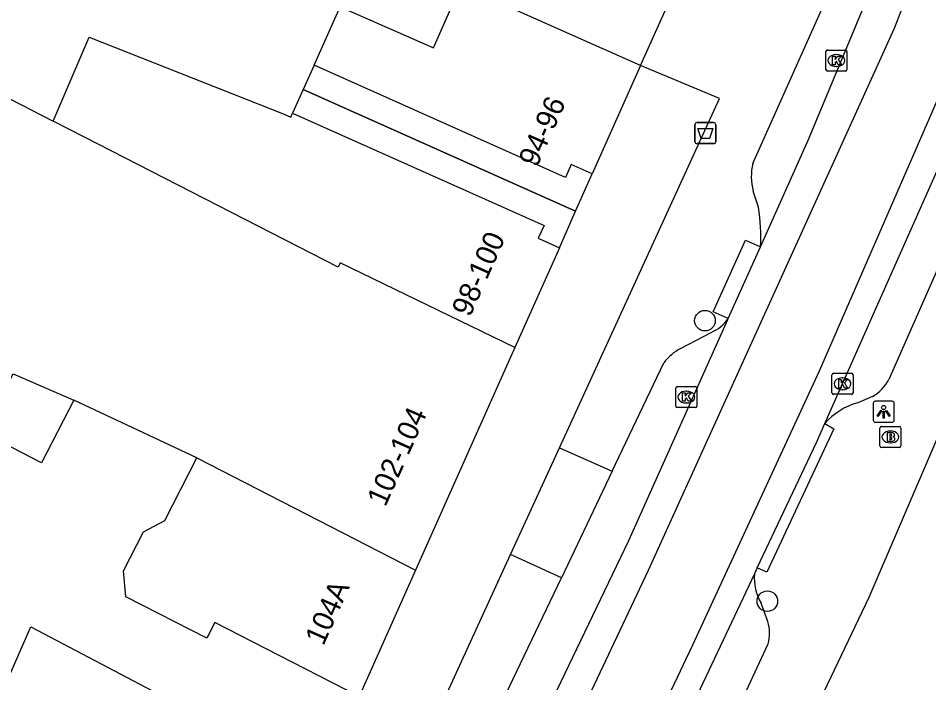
# Model space of a CAD drawing. Extents: x 160356 to 161355, y 381727 to 382845.
# Drawn here: x 160820.98 to 160864.31, y 382307.98 to 382339.61 of the extents above; entities that cross this region are included whole.
import ezdxf

# ---------------------------------------------------------------- set-up
doc = ezdxf.new("R2010")
doc.units = 0
for name, color, linetype in [('IMGEO_Afvalbak', 7, 'Continuous'), ('IMGEO_Boom', 7, 'Continuous'), ('IMGEO_Brandkraan', 7, 'Continuous'), ('IMGEO_Kolk', 7, 'Continuous'), ('IMGEO_Lichtpunt', 7, 'Continuous'), ('IMGEO_Pand', 7, 'Continuous'), ('IMGEO_Pand_nummerreeks', 7, 'Continuous'), ('IMGEO_Pand_overbouw', 7, 'Continuous'), ('IMGEO_Rijbaan_lokaal_gesloten', 7, 'Continuous'), ('IMGEO_Voetpad_open', 7, 'Continuous')]:
    doc.layers.add(name, color=color, linetype=linetype)

msp = doc.modelspace()

# ---------------------------------------------------------------- linework, layer by layer
at = {"layer": 'IMGEO_Afvalbak'}
for p, q in [((160853.179, 382333.741), (160853.179, 382334.541)), ((160853.179, 382334.541), (160853.179, 382333.741)), ((160853.279, 382334.641), (160854.069, 382334.641)), ((160854.069, 382334.641), (160853.279, 382334.641)), ((160854.169, 382334.541), (160854.169, 382333.741)), ((160854.169, 382333.741), (160854.169, 382334.541)), ((160854.069, 382333.641), (160853.279, 382333.641)), ((160853.279, 382333.641), (160854.069, 382333.641))]:
    msp.add_line(p, q, dxfattribs=at)
msp.add_lwpolyline([(160853.322, 382334.355), (160854.026, 382334.355), (160853.877, 382333.885), (160853.471, 382333.885), (160853.322, 382334.355)], dxfattribs=at)
for centre, start, end in [((160853.279, 382334.541), 90, 180), ((160853.279, 382334.541), 90, 180), ((160854.069, 382334.541), 0, 90), ((160854.069, 382334.541), 360, 90), ((160853.279, 382333.741), 180, 270), ((160853.279, 382333.741), 180, 270), ((160854.069, 382333.741), 270, 0), ((160854.069, 382333.741), 270, 0)]:
    msp.add_arc(centre, 0.1, start, end, dxfattribs=at)
at = {"layer": 'IMGEO_Boom'}
for centre in [(160853.654, 382325.214), (160856.624, 382311.862)]:
    msp.add_circle(centre, 0.489, dxfattribs=at)
at = {"layer": 'IMGEO_Brandkraan'}
for p, q in [((160861.978, 382319.251), (160861.978, 382320.103)), ((160862.053, 382320.177), (160862.905, 382320.177)), ((160862.979, 382320.103), (160862.979, 382319.251)), ((160862.466, 382319.957), (160862.491, 382319.957)), ((160862.905, 382319.177), (160862.053, 382319.177)), ((160862.489, 382319.397), (160862.464, 382319.397))]:
    msp.add_line(p, q, dxfattribs=at)
for points in [[(160861.978, 382319.251), (160861.978, 382320.103)], [(160862.053, 382320.177), (160862.905, 382320.177)], [(160862.979, 382320.103), (160862.979, 382319.251)], [(160862.326, 382319.877), (160862.326, 382319.477), (160862.539, 382319.477)], [(160862.557, 382319.877), (160862.326, 382319.877)], [(160862.505, 382319.796), (160862.451, 382319.796), (160862.451, 382319.72)], [(160862.451, 382319.72), (160862.504, 382319.72)], [(160862.513, 382319.644), (160862.451, 382319.644), (160862.451, 382319.563)], [(160862.451, 382319.563), (160862.513, 382319.563)], [(160862.905, 382319.177), (160862.053, 382319.177)]]:
    msp.add_lwpolyline(points, dxfattribs=at)
for centre, radius, start, end in [((160862.055, 382320.101), 0.0765, 91.552, 178.448), ((160862.055, 382320.101), 0.0765, 91.552, 178.448), ((160862.903, 382320.101), 0.0765, 1.552, 88.448), ((160862.903, 382320.101), 0.0765, 1.552, 88.448), ((160862.506, 382319.758), 0.0379, 267.8285, 90.9355), ((160862.514, 382319.603), 0.0404, 269.8759, 90.5077), ((160862.561, 382319.732), 0.145, 59.4692, 91.5367), ((160862.586, 382319.779), 0.0922, 285.5137, 58.1501), ((160862.591, 382319.587), 0.105, 301.3115, 78.989), ((160862.055, 382319.253), 0.0765, 181.552, 268.448), ((160862.055, 382319.253), 0.0765, 181.552, 268.448), ((160862.545, 382319.728), 0.251, 268.6676, 293.5347), ((160862.903, 382319.253), 0.0765, 271.552, 358.448), ((160862.903, 382319.253), 0.0765, 271.552, 358.448)]:
    msp.add_arc(centre, radius, start, end, dxfattribs=at)
for centre, major_axis, ratio, start_param, end_param in [((160862.465, 382319.677), (-0.387, 0.002), 0.722429, 4.712389, 7.853982), ((160862.49, 382319.677), (-0.39, 0.002), 0.717154, 1.570796, 4.712389)]:
    msp.add_ellipse(centre, major_axis=major_axis, ratio=ratio, start_param=start_param, end_param=end_param, dxfattribs=at)
at = {"layer": 'IMGEO_Kolk'}
for p, q in [((160859.408, 382337.172), (160859.408, 382338.024)), ((160859.483, 382338.098), (160860.335, 382338.098)), ((160859.896, 382337.878), (160859.921, 382337.878)), ((160860.409, 382338.024), (160860.409, 382337.172)), ((160859.919, 382337.318), (160859.894, 382337.318)), ((160860.335, 382337.098), (160859.483, 382337.098)), ((160859.7, 382321.781), (160859.7, 382322.633)), ((160859.775, 382322.707), (160860.627, 382322.707)), ((160860.701, 382322.633), (160860.701, 382321.781)), ((160860.188, 382322.487), (160860.213, 382322.487)), ((160852.269, 382321.149), (160852.269, 382322.001)), ((160852.344, 382322.075), (160853.196, 382322.075)), ((160852.757, 382321.855), (160852.782, 382321.855)), ((160853.27, 382322.001), (160853.27, 382321.149)), ((160860.211, 382321.927), (160860.186, 382321.927)), ((160852.78, 382321.295), (160852.755, 382321.295)), ((160860.627, 382321.707), (160859.775, 382321.707)), ((160853.196, 382321.075), (160852.344, 382321.075))]:
    msp.add_line(p, q, dxfattribs=at)
for points in [[(160859.408, 382337.172), (160859.408, 382338.024)], [(160859.483, 382338.098), (160860.335, 382338.098)], [(160859.729, 382337.798), (160859.852, 382337.798), (160859.852, 382337.647), (160859.982, 382337.798), (160860.146, 382337.798), (160860, 382337.647), (160860.153, 382337.398), (160860.001, 382337.398), (160859.916, 382337.562), (160859.852, 382337.495), (160859.852, 382337.398), (160859.729, 382337.398), (160859.729, 382337.798)], [(160860.409, 382338.024), (160860.409, 382337.172)], [(160860.335, 382337.098), (160859.483, 382337.098)], [(160859.7, 382321.781), (160859.7, 382322.633)], [(160859.775, 382322.707), (160860.627, 382322.707)], [(160860.701, 382322.633), (160860.701, 382321.781)], [(160860.021, 382322.407), (160860.144, 382322.407), (160860.144, 382322.256), (160860.274, 382322.407), (160860.438, 382322.407), (160860.292, 382322.256), (160860.445, 382322.007), (160860.293, 382322.007), (160860.208, 382322.171), (160860.144, 382322.104), (160860.144, 382322.007), (160860.021, 382322.007), (160860.021, 382322.407)], [(160852.269, 382321.149), (160852.269, 382322.001)], [(160852.344, 382322.075), (160853.196, 382322.075)], [(160852.59, 382321.775), (160852.713, 382321.775), (160852.713, 382321.624), (160852.843, 382321.775), (160853.007, 382321.775), (160852.861, 382321.624), (160853.014, 382321.375), (160852.862, 382321.375), (160852.777, 382321.539), (160852.713, 382321.472), (160852.713, 382321.375), (160852.59, 382321.375), (160852.59, 382321.775)], [(160853.27, 382322.001), (160853.27, 382321.149)], [(160860.627, 382321.707), (160859.775, 382321.707)], [(160853.196, 382321.075), (160852.344, 382321.075)]]:
    msp.add_lwpolyline(points, dxfattribs=at)
for centre, start, end in [((160859.485, 382338.022), 91.552, 178.448), ((160859.485, 382338.022), 91.552, 178.448), ((160860.333, 382338.022), 1.552, 88.448), ((160860.333, 382338.022), 1.552, 88.448), ((160859.485, 382337.174), 181.552, 268.448), ((160859.485, 382337.174), 181.552, 268.448), ((160860.333, 382337.174), 271.552, 358.448), ((160860.333, 382337.174), 271.552, 358.448), ((160859.777, 382322.631), 91.552, 178.448), ((160859.777, 382322.631), 91.552, 178.448), ((160860.625, 382322.631), 1.552, 88.448), ((160860.625, 382322.631), 1.552, 88.448), ((160852.346, 382321.999), 91.552, 178.448), ((160852.346, 382321.999), 91.552, 178.448), ((160853.194, 382321.999), 1.552, 88.448), ((160853.194, 382321.999), 1.552, 88.448), ((160859.777, 382321.783), 181.552, 268.448), ((160859.777, 382321.783), 181.552, 268.448), ((160860.625, 382321.783), 271.552, 358.448), ((160860.625, 382321.783), 271.552, 358.448), ((160852.346, 382321.151), 181.552, 268.448), ((160852.346, 382321.151), 181.552, 268.448), ((160853.194, 382321.151), 271.552, 358.448), ((160853.194, 382321.151), 271.552, 358.448)]:
    msp.add_arc(centre, 0.0765, start, end, dxfattribs=at)
for centre, major_axis, ratio, start_param, end_param in [((160859.895, 382337.598), (-0.387, 0.002), 0.722429, 4.712389, 7.853982), ((160859.92, 382337.598), (-0.39, 0.002), 0.717154, 1.570796, 4.712389), ((160860.187, 382322.207), (-0.387, 0.002), 0.722429, 4.712389, 7.853982), ((160860.212, 382322.207), (-0.39, 0.002), 0.717154, 1.570796, 4.712389), ((160852.756, 382321.575), (-0.387, 0.002), 0.722429, 4.712389, 7.853982), ((160852.781, 382321.575), (-0.39, 0.002), 0.717154, 1.570796, 4.712389)]:
    msp.add_ellipse(centre, major_axis=major_axis, ratio=ratio, start_param=start_param, end_param=end_param, dxfattribs=at)
at = {"layer": 'IMGEO_Lichtpunt'}
for p, q in [((160861.663, 382321.282), (160861.663, 382320.475)), ((160861.663, 382321.282), (160861.663, 382320.475)), ((160862.565, 382321.377), (160861.757, 382321.377)), ((160862.565, 382321.377), (160861.757, 382321.377)), ((160862.659, 382320.475), (160862.659, 382321.282)), ((160862.659, 382320.475), (160862.659, 382321.282)), ((160861.757, 382320.381), (160862.565, 382320.381)), ((160861.757, 382320.381), (160862.565, 382320.381))]:
    msp.add_line(p, q, dxfattribs=at)
for points in [[(160862.037, 382320.946), (160862.076, 382320.918), (160861.888, 382320.656), (160861.85, 382320.683), (160862.037, 382320.946)], [(160862.139, 382320.898), (160862.186, 382320.898), (160862.186, 382320.576), (160862.139, 382320.576), (160862.139, 382320.898)], [(160862.249, 382320.918), (160862.287, 382320.945), (160862.474, 382320.683), (160862.435, 382320.655), (160862.249, 382320.918)]]:
    msp.add_lwpolyline(points, dxfattribs=at)
msp.add_circle((160862.162, 382321.08), 0.0994, dxfattribs=at)
for centre, start, end in [((160861.757, 382321.282), 90, 180), ((160861.757, 382321.282), 90, 180), ((160862.565, 382321.282), 0, 90), ((160862.565, 382321.282), 0, 90), ((160861.757, 382320.475), 180, 270), ((160861.757, 382320.475), 180, 270), ((160862.565, 382320.475), 270, 0), ((160862.565, 382320.475), 270, 360)]:
    msp.add_arc(centre, 0.0946, start, end, dxfattribs=at)
at = {"layer": 'IMGEO_Pand'}
for points in [[(160813.558, 382344.41), (160814.082, 382344.143), (160812.151, 382340.084), (160816.462, 382337.876), (160822.641, 382334.707)], [(160850.594, 382337.355), (160852.95, 382342.635)], [(160850.594, 382337.355), (160848.294, 382332.2), (160847.289, 382332.648), (160847.015, 382332.033), (160835.051, 382337.37), (160836.291, 382340.148), (160840.739, 382338.197), (160842.045, 382341.175), (160842.476, 382340.982)], [(160850.594, 382337.355), (160846.946, 382338.985), (160842.476, 382340.982)], [(160822.641, 382334.707), (160824.349, 382338.702), (160833.629, 382335.048), (160833.951, 382334.904), (160834.033, 382335.087), (160845.996, 382329.75), (160845.721, 382329.134), (160846.726, 382328.686), (160844.607, 382323.937)], [(160844.607, 382323.937), (160836.29, 382327.967), (160836.2, 382327.763), (160824.13, 382333.943), (160822.641, 382334.707)], [(160844.607, 382323.937), (160839.877, 382313.337)], [(160823.62, 382321.432), (160822.091, 382318.445), (160819.304, 382319.872), (160820.741, 382322.676)], [(160820.741, 382322.676), (160823.62, 382321.432)], [(160829.477, 382318.678), (160823.62, 382321.432)], [(160839.877, 382313.337), (160837.197, 382307.331), (160832.747, 382309.61), (160830.326, 382310.85), (160829.944, 382310.103), (160826.098, 382312.071), (160825.98, 382313.304), (160826.934, 382315.169), (160827.951, 382315.694), (160829.477, 382318.678)], [(160829.477, 382318.678), (160839.877, 382313.337)], [(160821.622, 382302.222), (160818.559, 382303.797), (160821.582, 382310.638), (160833.15, 382304.546), (160832.586, 382303.474), (160834.745, 382302.338), (160832.085, 382296.731)]]:
    msp.add_lwpolyline(points, dxfattribs=at)
at = {"layer": 'IMGEO_Pand_overbouw'}
for points in [[(160835.051, 382337.37), (160834.534, 382336.21), (160847.502, 382330.425), (160848.294, 382332.2), (160847.289, 382332.648), (160847.015, 382332.033)], [(160834.534, 382336.21), (160834.033, 382335.087), (160845.996, 382329.75), (160845.721, 382329.134), (160846.726, 382328.686), (160847.502, 382330.425)]]:
    msp.add_lwpolyline(points, close=True, dxfattribs=at)
at = {"layer": 'IMGEO_Rijbaan_lokaal_gesloten'}
for points in [[(160871.535, 382363.229), (160868.864, 382355.162), (160862.656, 382339.12), (160850.947, 382313.328), (160845.281, 382301.287), (160837.239, 382284.953), (160826.989, 382265.037), (160812.989, 382240.37), (160784.239, 382192.537), (160777.906, 382181.828), (160776.425, 382182.776)], [(160874.812, 382362.252), (160874.567, 382361.431), (160873.42, 382357.694), (160870.928, 382350.579), (160869.059, 382345.759), (160864.338, 382334.874), (160859.092, 382322.809), (160853.059, 382309.759), (160846.567, 382296.087), (160839.879, 382282.612), (160835.649, 382274.12), (160830.666, 382264.645), (160824.699, 382254.022), (160816.567, 382239.989), (160805.748, 382221.628), (160792.985, 382200.423), (160781.379, 382180.62), (160782.592, 382179.909)], [(160856.293, 382328.731), (160858.578, 382333.835), (160862.813, 382344.017)], [(160859.359, 382320.315), (160867.708, 382339.101)], [(160854.763, 382325.314), (160856.293, 382328.731)], [(160844.333, 382302.883), (160850.03, 382314.742), (160854.74, 382325.262), (160854.763, 382325.314)], [(160856.147, 382313.455), (160858.959, 382319.416), (160859.359, 382320.315)], [(160856.008, 382313.16), (160849.068, 382298.447)], [(160856.147, 382313.455), (160856.008, 382313.16)]]:
    msp.add_lwpolyline(points, dxfattribs=at)
at = {"layer": 'IMGEO_Voetpad_open'}
for points in [[(160855.933, 382332.702), (160859.952, 382341.698)], [(160872.549, 382337.919), (160861.447, 382312.039), (160855.676, 382299.934), (160853.77, 382296.133), (160836.402, 382261.505)], [(160846.734, 382319.167), (160854.342, 382335.793), (160850.594, 382337.355)], [(160868.227, 382335.619), (160862.412, 382322.418)], [(160856.203, 382330.609), (160855.956, 382331.381)], [(160854.763, 382325.314), (160854.053, 382325.64), (160855.587, 382329.052), (160856.293, 382328.731)], [(160852.497, 382323.888), (160853.948, 382324.648)], [(160849.243, 382318.052), (160851.702, 382323.208)], [(160861.631, 382321.599), (160860.923, 382321.302)], [(160859.359, 382320.315), (160859.794, 382320.065), (160856.598, 382313.24), (160856.147, 382313.455)], [(160844.409, 382314.087), (160846.734, 382319.167)], [(160846.734, 382319.167), (160849.243, 382318.052)], [(160849.243, 382318.052), (160846.821, 382312.974)], [(160772.407, 382184.113), (160794.573, 382221.181), (160811.234, 382250), (160815.558, 382257.479), (160828.746, 382282.08), (160838.339, 382300.821), (160840.283, 382305.069), (160844.409, 382314.087)], [(160846.821, 382312.974), (160844.409, 382314.087)], [(160843.818, 382306.679), (160846.821, 382312.974)], [(160856.648, 382310.894), (160856.323, 382311.767)], [(160852.214, 382300.261), (160856.669, 382309.828)]]:
    msp.add_lwpolyline(points, dxfattribs=at)
for centre, radius, start, end in [((160858.453, 382332.085), 2.594, 166.2459, 195.7491), ((160848.449, 382329.296), 7.864, 355.8783, 9.6091), ((160853.117, 382326.497), 2.027, 294.2063, 324.3036), ((160853.546, 382321.856), 2.287, 117.3181, 143.7657), ((160860.442, 382323.515), 2.255, 301.8266, 330.8945), ((160861.792, 382318.193), 3.229, 105.6116, 138.8983), ((160858.435, 382312.977), 2.434, 175.681, 209.8031), ((160854.649, 382310.321), 2.079, 346.2719, 15.9853)]:
    msp.add_arc(centre, radius, start, end, dxfattribs=at)

# ---------------------------------------------------------------- texts
at = {"layer": 'IMGEO_Pand_nummerreeks'}
for s, rotation, p in [('94-96', 65.9532, (160845.657, 382332.472)), ('98-100', 65.9527, (160842.477, 382325.347)), ('102-104', 65.9532, (160838.446, 382316.315)), ('104A', 65.9532, (160835.496, 382309.702))]:
    msp.add_text(s, height=1, rotation=rotation, dxfattribs=at).set_placement(p)

doc.saveas('drawing.dxf')
